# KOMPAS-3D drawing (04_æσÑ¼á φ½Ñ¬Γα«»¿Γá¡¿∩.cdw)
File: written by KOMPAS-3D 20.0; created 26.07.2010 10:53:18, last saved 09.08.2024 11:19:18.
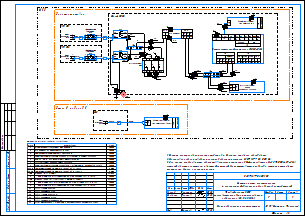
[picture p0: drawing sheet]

Sheet 1: A3, landscape

Document properties: Автор: Силов Дмитрий Дмитриевич; Проверил: Тарасов; Полное имя файла: \\s-tech\depts\Отдел_ПКО\Проекты\Типовые проекты МКД 2023\!Типовой проект\2_Типовой проект МКД_Радиоканал\04_Схема электропитания.cdw

Title block, sheet 1: Наименование: Типовой проект ИСУЭ / многоквартирного дома с использлованием / проводного канала связи RS-485; designation: ВЛСТ 1277.02.001 C5; Материал: Схема подключения электропитания; scale: 1:5; Количество листов документа: 1; organisation: АО ГК "Системы и Технологии"; Форматы листов документа: A3; Литера: К; Литера: 1; stored path: Z:\!Оборудование СТ\АСУ НО\Модификации\50А\Новое\Сборочный чертеж.cdw; Разработал: Воронина; Утвердил: Шмончев; cell 302: Система учета электроэнергии / (с организацией удаленного сбора данных) потребителей; cell 303: Типовой проект ИСУЭ / многоквартирного дома с использованием / радиоканала (F2/868 МГц); cell 320: Р

Referenced files in \\Helios\отдел_пко\Общая папка Компас\_Addons\Signatures\: Signatures.lfr|Тарасов, Signatures.lfr, Signatures.lfr|Шмончев
Referenced files in C:\Program Files\ASCON\KOMPAS-3D V13\Libs\_Addons\Signatures\: Signatures.lfr
Referenced files: qlkzkl.frw, hsklda.frw, jndvba.frw
Referenced files in Y:\Общая папка Компас\_Addons\Signatures\: Signatures.lfr|Голдина, Signatures.lfr
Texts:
  Тарасов
  Голдина
  Table Heading
  Table Contents
  Normal
  Материал-Предприятие
  Лит-Масса-Масштаб
  ООббыыччнныыйй
  Definition Term
  Definition List
  Address
  Blockquote
  Preformatted
  Courier New
  z-Bottom of Form
  z-Top of Form
  ISOCPEUR
  Centerline
  Outline
  Электрощитовая
  МКД
  ХТ1
  QF2
  QF1
  Переключатель
  фаз
  Шкаф УСПД
  Интеллектуальный контроллер SM160-02М
  COM4
  COM3
  COM2
  COM1
  Питание
  RS-232
  RxD
  TxD
  GND
  ТС2-
  ТС1-
  ТС+
  GSM
  Etherhet
  USB-A
  ХТ2
  RF-формирователь
  Link ST200.F2-K1
  RF Антенна
  ВРУ №2
  ВРУ №1
  Автоматический
  выключатель
  QF3
  Точка
  подключения
  QF4
  Преобразователь
  линии
  ВЛСТ 217.00.000-04
  Этаж N подъезд K
  Link ST200.F2-09-SMA
  Таблица 1 - Перечень основного оборудования
  № поз.
  Колич.
  Электронный переключатель фаз ПЭФ-301
  Блок питания 30 Вт (ВЛСТ 1000.10.002)
  Интеллектуальный контроллер SM160-02M
  RF-формирователь Link ST200.F2-K1 "координатор" ВЛСТ 339.10.000-K1
  QF1, QF2
  QF3, QF4
  Шина РЕ "земля" на DIN-изоляторе ШНИ-6х9-6-Д-Ж
  Преобразователь линии ВЛСТ 217.00.000-04
  Клеммник ("N") в составе:
  Автоматический выключатель ВА47-29 2Р 6А х-ка С
  RF-формирователь Link ST200.F2-09-SMA "повторитель" ВЛСТ 339.04.000-9s
  Автоматический выключатель ВА47-29 2Р 10А х-ка С
  HMM.2/2+2(Ex)i, проходной зажим 2,5 кв.мм синий 2 ввод/2 вывода
  Клеммник ("=24В для оборудования в шкафу") в составе:
  HMM.2/2+2GR(Ex), проходной зажим 2,5 кв.мм серый 2 ввод/2 вывода
  Провод белый ПуГВ 1х2,5
  Провод синий ПуГВ 1х2,5
  Провод белый ПуГВ 1х0,75
  Провод синий ПуГВ 1х0,75
  Провод желто-зеленый ПуГВ 1х4
  Кабель mini USB-USB, в комплекте с Link ST200.F2-K1 ВЛСТ339.10.000-K1
  1. Позиции пронумерованы согласно таблице 1 - Перечень основного оборудования.
  2. Маркировка кабеля приведена согласно Кабельному журналу ВЛСТ 1277. 02. 000 С6.
  3. Для опроса приборов учета абонентов возможно применение RF-формирователя Link ST200.F2-09-SMA,
  который является репитером с внешней антенной. Разместить внутри подъезда, антенну установить
  максимально близко к оконному проему.
  Блок питания
  POLYLINE_STYLE_0.30_RGB_0_255_255
  SLD-Сплошная_RGB_0_255_255_THICK_0.3
  POLYLINE_STYLE_0.25_RGB_0_0_0
  тон пунк.0.5-0,5
  JIS_02_2.0_RGB_255_0_255_SC_3_THICK_0.13
  Красная
  POLYLINE_STYLE_0.40_RGB_0_0_255
  POLYLINE_STYLE_0.30_RGB_0_0_255
  POLYLINE_STYLE_0.20_RGB_0_0_0
  POLYLINE_STYLE_0.20_RGB_0_255_255
  Штриховая 2.0х1.0
  JIS_02_0.7_RGB_0_0_0_SC_1_THICK_0.18
  Стили документа
  Разраб.
  Утв.
  03 Рабочие чертежи основного комплекта. ГОСТ Р 21.1101-2009 Ф3
Dimensions and other numbers on the sheet: 5и0; 4и0; 1; 2; 3; 4; 5; 6; 7; 8; 9; 10; 11; 12; 1   2  3   4   5  6; 220В; 1 шт.; 1 компл.; 2 шт.; 1   2   3   4; 24 В; 220 В; 6   5; 0,5-0,5; 0,5-0,5 Основная; 1:5; 03.23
